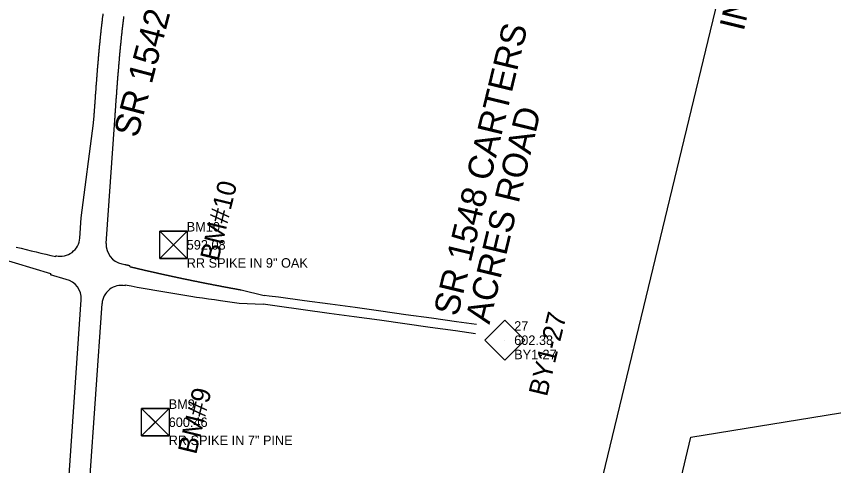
# Model space of a CAD drawing. Extents: x 1649669 to 1659218, y 588594 to 607900.
# Drawn here: x 1655108 to 1656826, y 603109 to 604053 of the extents above; entities that cross this region are included whole.
import ezdxf

# ---------------------------------------------------------------- set-up
doc = ezdxf.new("R2010")
doc.units = 0
for name, color, linetype in [('CTL Bench Mark CELL', 7, 'Continuous'), ('CTL Bench Mark Cogo Comment', 7, 'Continuous'), ('CTL Bench Mark Cogo Elevation', 7, 'Continuous'), ('CTL Bench Mark Cogo Number', 7, 'Continuous'), ('CTL Bench Mark Text', 7, 'Continuous'), ('CTL Sheet Notes CELL', 7, 'Continuous'), ('CTL Supplemental Horizontal and Vertical CELL', 7, 'Continuous'), ('CTL Supplemental Horizontal and Vertical Cogo Comment', 7, 'Continuous'), ('CTL Supplemental Horizontal and Vertical Cogo Elevation', 7, 'Continuous'), ('CTL Supplemental Horizontal and Vertical Cogo Number', 7, 'Continuous'), ('CTL Supplemental Horizontal and Vertical Text', 7, 'Continuous'), ('Default', 7, 'Continuous'), ('Exist Roads EOP', 7, 'Continuous'), ('Sheet Data Field CELL', 7, 'Continuous')]:
    doc.layers.add(name, color=color, linetype=linetype)

msp = doc.modelspace()

# ---------------------------------------------------------------- linework, layer by layer
at = {"layer": 'CTL Bench Mark CELL'}
for p, q in [((1655438.2, 603572.9), (1655438.2, 603572.9)), ((1655400.3, 603200), (1655400.3, 603200))]:
    msp.add_line(p, q, dxfattribs=at)
for points in [[(1655409.4, 603601.6), (1655466.9, 603601.6), (1655466.9, 603544.1), (1655409.4, 603544.1)], [(1655371.5, 603228.7), (1655429, 603228.7), (1655429, 603171.2), (1655371.5, 603171.2)]]:
    msp.add_lwpolyline(points, close=True, dxfattribs=at)
for points in [[(1655466.9, 603601.6), (1655409.4, 603544.1), (1655438.1, 603572.9), (1655466.9, 603544.1), (1655409.4, 603601.6)], [(1655438.1, 603572.9), (1655466.9, 603601.6), (1655409.4, 603601.6), (1655438.1, 603572.9)], [(1655438.1, 603572.9), (1655409.4, 603544.1), (1655466.9, 603544.1), (1655438.1, 603572.9)], [(1655429, 603228.7), (1655371.5, 603171.2), (1655400.3, 603199.9), (1655429, 603171.2), (1655371.5, 603228.7)], [(1655400.3, 603199.9), (1655429, 603228.7), (1655371.5, 603228.7), (1655400.3, 603199.9)], [(1655400.3, 603199.9), (1655371.5, 603171.2), (1655429, 603171.2), (1655400.3, 603199.9)]]:
    msp.add_lwpolyline(points, dxfattribs=at)
at = {"layer": 'CTL Sheet Notes CELL'}
msp.add_lwpolyline([(1656065.2, 601942.6), (1657135.7, 606376.1), (1658875.8, 605955.9), (1657805.4, 601522.5)], close=True, dxfattribs=at)
at = {"layer": 'CTL Supplemental Horizontal and Vertical CELL'}
msp.add_line((1656134.7, 603372.4), (1656134.7, 603372.4), dxfattribs=at)
msp.add_lwpolyline([(1656093, 603372.5), (1656134.9, 603414.5), (1656176.9, 603372.5), (1656135, 603330.5)], close=True, dxfattribs=at)
at = {"layer": 'Default'}
for p, q in [((1656526.1, 603168.4), (1657183.3, 603275.1)), ((1656351.8, 602446.9), (1656526.1, 603168.4))]:
    msp.add_line(p, q, dxfattribs=at)
at = {"layer": 'Exist Roads EOP'}
for p, q in [((1655244.6, 603629.8), (1655270.5, 603828.5)), ((1655270.5, 603828.5), (1655271.2, 603837.9)), ((1655297, 603576.1), (1655315, 603834.8)), ((1655241.6, 603587.2), (1655244.6, 603629.8)), ((1655180.2, 603512), (1654970.5, 603574.3)), ((1655191.5, 603550.2), (1655191.1, 603548.2)), ((1655346.3, 603527.3), (1655346.8, 603529.2)), ((1655396.4, 603515.6), (1655396.4, 603515.6)), ((1655180.2, 603512), (1655179.6, 603510.1)), ((1655212.6, 603500.2), (1655179.6, 603510.1)), ((1655457.5, 603502.2), (1655457.5, 603502.2)), ((1655336.7, 603486.9), (1655337.1, 603488.8)), ((1655518.8, 603489.9), (1655518.8, 603489.9)), ((1655580.4, 603478.2), (1655629.4, 603466.6)), ((1655210.9, 602974.5), (1655244.6, 603457.4)), ((1655254.8, 602971.5), (1655288.2, 603449.4)), ((1655537.3, 603455.9), (1655576.7, 603450.5)), ((1655576.7, 603450.5), (1655626.8, 603447.9)), ((1655713.8, 603455.2), (1655659.3, 603462.6)), ((1655768.1, 603448), (1655713.8, 603455.2)), ((1655820.7, 603441), (1655768.1, 603448)), ((1655711.2, 603436.4), (1655656.7, 603443.8)), ((1655765.4, 603428.9), (1655711.2, 603436.4)), ((1655818.2, 603421.8), (1655765.4, 603428.9)), ((1655874.3, 603433.7), (1655820.7, 603441)), ((1655927.1, 603426.1), (1655874.3, 603433.7)), ((1655871.6, 603414.5), (1655818.2, 603421.8)), ((1655924.8, 603407.1), (1655871.6, 603414.5)), ((1655981, 603418.6), (1655927.1, 603426.1)), ((1656033.6, 603411.2), (1655981, 603418.6)), ((1655978.3, 603399.5), (1655924.8, 603407.1)), ((1656031, 603391.9), (1655978.3, 603399.5)), ((1656075.5, 603405.3), (1656033.6, 603411.2)), ((1656073.6, 603386), (1656031, 603391.9))]:
    msp.add_line(p, q, dxfattribs=at)
for points in [[(1655659.3, 603462.6), (1655639.3, 603465.3), (1655629.4, 603466.6)], [(1655656.7, 603443.8), (1655636.7, 603446.5), (1655626.8, 603447.9)]]:
    msp.add_lwpolyline(points, dxfattribs=at)
for centre, radius, start, end in [((1655200.7, 603590.1), 41, 256.9954, 356.0095), ((1656088, 607432), 3986, 255.7673, 256.9954), ((1655337.9, 603573.2), 41, 176.0095, 258.999), ((1656088, 607432), 3972, 258.999, 259.0872), ((1655203.7, 603460.2), 41, 356.0095, 77.4476), ((1655329.1, 603446.6), 41, 79.2178, 176.0095), ((1656088, 607432), 4014, 259.2178, 262.1141)]:
    msp.add_arc(centre, radius, start, end, dxfattribs=at)
for points in [[(1655271.2, 603837.9), (1655271.4, 603841.6), (1655271.7, 603845.4), (1655271.9, 603849.2), (1655272.2, 603853), (1655272.5, 603856.8), (1655272.7, 603860.5), (1655273, 603864.3), (1655273.3, 603868.1), (1655273.5, 603871.9), (1655273.8, 603875.7), (1655274.1, 603879.4), (1655274.4, 603883.2), (1655274.6, 603887), (1655274.9, 603890.8), (1655275.2, 603894.6), (1655275.5, 603898.3), (1655275.7, 603902.1), (1655276, 603905.9), (1655276.3, 603909.7), (1655276.6, 603913.5), (1655276.9, 603917.3), (1655277.2, 603921.1), (1655277.5, 603924.9), (1655277.8, 603928.6), (1655278.1, 603932.4), (1655278.4, 603936.2), (1655278.7, 603940), (1655279, 603943.8), (1655279.3, 603947.6), (1655279.6, 603951.4), (1655279.9, 603955.2), (1655280.3, 603959), (1655280.6, 603962.8), (1655280.9, 603966.6), (1655281.3, 603970.3), (1655281.6, 603974.1), (1655282, 603977.9), (1655282.3, 603981.7), (1655282.7, 603985.5), (1655283, 603989.3), (1655283.4, 603993.1), (1655283.8, 603996.9), (1655284.1, 604000.7), (1655284.5, 604004.5), (1655284.9, 604008.3), (1655285.3, 604012.1), (1655285.7, 604015.9), (1655286.1, 604019.7), (1655286.5, 604023.5), (1655286.9, 604027.3), (1655287.3, 604031.1), (1655287.8, 604034.9), (1655288.2, 604038.7), (1655288.6, 604042.5), (1655289.1, 604046.3), (1655289.5, 604050), (1655290, 604053.8), (1655290.5, 604057.6), (1655290.6, 604058.7)], [(1655315, 603834.8), (1655315.3, 603838.6), (1655315.6, 603842.4), (1655315.8, 603846.1), (1655316.1, 603849.9), (1655316.4, 603853.7), (1655316.6, 603857.4), (1655316.9, 603861.2), (1655317.2, 603865), (1655317.4, 603868.8), (1655317.7, 603872.5), (1655318, 603876.3), (1655318.2, 603880.1), (1655318.5, 603883.8), (1655318.8, 603887.6), (1655319.1, 603891.3), (1655319.3, 603895.1), (1655319.6, 603898.9), (1655319.9, 603902.6), (1655320.2, 603906.4), (1655320.5, 603910.1), (1655320.8, 603913.9), (1655321, 603917.7), (1655321.3, 603921.4), (1655321.6, 603925.2), (1655321.9, 603928.9), (1655322.2, 603932.7), (1655322.5, 603936.4), (1655322.8, 603940.2), (1655323.2, 603943.9), (1655323.5, 603947.7), (1655323.8, 603951.4), (1655324.1, 603955.2), (1655324.4, 603958.9), (1655324.8, 603962.7), (1655325.1, 603966.4), (1655325.4, 603970.2), (1655325.8, 603973.9), (1655326.1, 603977.7), (1655326.5, 603981.4), (1655326.8, 603985.1), (1655327.2, 603988.9), (1655327.5, 603992.6), (1655327.9, 603996.3), (1655328.3, 604000.1), (1655328.7, 604003.8), (1655329.1, 604007.5), (1655329.4, 604011.3), (1655329.8, 604015), (1655330.2, 604018.7), (1655330.6, 604022.5), (1655331.1, 604026.2), (1655331.5, 604029.9), (1655331.9, 604033.6), (1655332.3, 604037.4), (1655332.8, 604041.1), (1655333.2, 604044.8), (1655333.7, 604048.5), (1655334.1, 604052.2), (1655334.3, 604053.3)], [(1655336.1, 603531.8), (1655336.9, 603531.6), (1655337.7, 603531.4), (1655338.5, 603531.2), (1655339.3, 603531), (1655340.2, 603530.8), (1655341, 603530.6), (1655341.8, 603530.4), (1655342.6, 603530.2), (1655343.4, 603530), (1655344.3, 603529.8), (1655345.1, 603529.6), (1655345.9, 603529.4), (1655346.7, 603529.2), (1655346.8, 603529.2)], [(1655346.3, 603527.3), (1655347.1, 603527.1), (1655347.9, 603526.9), (1655348.7, 603526.7), (1655349.5, 603526.5), (1655350.4, 603526.3), (1655351.2, 603526.1), (1655352, 603525.9), (1655352.8, 603525.7), (1655353.6, 603525.5), (1655354.5, 603525.3), (1655355.3, 603525.1), (1655356.1, 603524.9), (1655356.9, 603524.7), (1655357.8, 603524.5), (1655358.6, 603524.3), (1655359.4, 603524.1), (1655360.2, 603524), (1655361, 603523.8), (1655361.9, 603523.6), (1655362.7, 603523.4), (1655363.5, 603523.2), (1655364.3, 603523), (1655365.1, 603522.8), (1655366, 603522.6), (1655366.8, 603522.4), (1655367.6, 603522.2), (1655368.4, 603522), (1655369.3, 603521.8), (1655370.1, 603521.6), (1655370.9, 603521.4), (1655371.7, 603521.2), (1655372.5, 603521.1), (1655373.4, 603520.9), (1655374.2, 603520.7), (1655375, 603520.5), (1655375.8, 603520.3), (1655376.7, 603520.1), (1655377.5, 603519.9), (1655378.3, 603519.7), (1655379.1, 603519.5), (1655379.9, 603519.3), (1655380.8, 603519.1), (1655381.6, 603519), (1655382.4, 603518.8), (1655383.2, 603518.6), (1655384.1, 603518.4), (1655384.9, 603518.2), (1655385.7, 603518), (1655386.5, 603517.8), (1655387.3, 603517.6), (1655388.2, 603517.4), (1655389, 603517.3), (1655389.8, 603517.1), (1655390.6, 603516.9), (1655391.5, 603516.7), (1655392.3, 603516.5), (1655393.1, 603516.3), (1655393.9, 603516.1), (1655394.8, 603515.9), (1655395.6, 603515.8), (1655396.4, 603515.6)], [(1655396.4, 603515.6), (1655397.2, 603515.4), (1655398, 603515.2), (1655398.9, 603515), (1655399.7, 603514.8), (1655400.5, 603514.6), (1655401.3, 603514.5), (1655402.2, 603514.3), (1655403, 603514.1), (1655403.8, 603513.9), (1655404.6, 603513.7), (1655405.5, 603513.5), (1655406.3, 603513.3), (1655407.1, 603513.2), (1655407.9, 603513), (1655408.8, 603512.8), (1655409.6, 603512.6), (1655410.4, 603512.4), (1655411.2, 603512.2), (1655412.1, 603512.1), (1655412.9, 603511.9), (1655413.7, 603511.7), (1655414.5, 603511.5), (1655415.4, 603511.3), (1655416.2, 603511.1), (1655417, 603511), (1655417.8, 603510.8), (1655418.6, 603510.6), (1655419.5, 603510.4), (1655420.3, 603510.2), (1655421.1, 603510.1), (1655421.9, 603509.9), (1655422.8, 603509.7), (1655423.6, 603509.5), (1655424.4, 603509.3), (1655425.2, 603509.1), (1655426.1, 603509), (1655426.9, 603508.8), (1655427.7, 603508.6), (1655428.5, 603508.4), (1655429.4, 603508.2), (1655430.2, 603508.1), (1655431, 603507.9), (1655431.9, 603507.7), (1655432.7, 603507.5), (1655433.5, 603507.4), (1655434.3, 603507.2), (1655435.2, 603507), (1655436, 603506.8), (1655436.8, 603506.6), (1655437.6, 603506.5), (1655438.5, 603506.3), (1655439.3, 603506.1), (1655440.1, 603505.9), (1655440.9, 603505.7), (1655441.8, 603505.6), (1655442.6, 603505.4), (1655443.4, 603505.2), (1655444.2, 603505), (1655445.1, 603504.9), (1655445.9, 603504.7), (1655446.7, 603504.5), (1655447.5, 603504.3), (1655448.4, 603504.2), (1655449.2, 603504), (1655450, 603503.8), (1655450.8, 603503.6), (1655451.7, 603503.5), (1655452.5, 603503.3), (1655453.3, 603503.1), (1655454.2, 603502.9), (1655455, 603502.8), (1655455.8, 603502.6), (1655456.6, 603502.4), (1655457.5, 603502.2)], [(1655457.5, 603502.2), (1655458.3, 603502.1), (1655459.1, 603501.9), (1655459.9, 603501.7), (1655460.8, 603501.5), (1655461.6, 603501.4), (1655462.4, 603501.2), (1655463.3, 603501), (1655464.1, 603500.9), (1655464.9, 603500.7), (1655465.7, 603500.5), (1655466.6, 603500.3), (1655467.4, 603500.2), (1655468.2, 603500), (1655469, 603499.8), (1655469.9, 603499.7), (1655470.7, 603499.5), (1655471.5, 603499.3), (1655472.4, 603499.1), (1655473.2, 603499), (1655474, 603498.8), (1655474.8, 603498.6), (1655475.7, 603498.5), (1655476.5, 603498.3), (1655477.3, 603498.1), (1655478.1, 603498), (1655479, 603497.8), (1655479.8, 603497.6), (1655480.6, 603497.4), (1655481.5, 603497.3), (1655482.3, 603497.1), (1655483.1, 603496.9), (1655483.9, 603496.8), (1655484.8, 603496.6), (1655485.6, 603496.4), (1655486.4, 603496.3), (1655487.3, 603496.1), (1655488.1, 603495.9), (1655488.9, 603495.8), (1655489.7, 603495.6), (1655490.6, 603495.4), (1655491.4, 603495.3), (1655492.2, 603495.1), (1655493.1, 603494.9), (1655493.9, 603494.8), (1655494.7, 603494.6), (1655495.5, 603494.4), (1655496.4, 603494.3), (1655497.2, 603494.1), (1655498, 603493.9), (1655498.9, 603493.8), (1655499.7, 603493.6), (1655500.5, 603493.4), (1655501.4, 603493.3), (1655502.2, 603493.1), (1655503, 603492.9), (1655503.8, 603492.8), (1655504.7, 603492.6), (1655505.5, 603492.5), (1655506.3, 603492.3), (1655507.2, 603492.1), (1655508, 603492), (1655508.8, 603491.8), (1655509.6, 603491.6), (1655510.5, 603491.5), (1655511.3, 603491.3), (1655512.1, 603491.2), (1655513, 603491), (1655513.8, 603490.8), (1655514.6, 603490.7), (1655515.5, 603490.5), (1655516.3, 603490.3), (1655517.1, 603490.2), (1655517.9, 603490), (1655518.8, 603489.9)], [(1655518.8, 603489.9), (1655519.6, 603489.7), (1655520.4, 603489.5), (1655521.3, 603489.4), (1655522.1, 603489.2), (1655522.9, 603489.1), (1655523.8, 603488.9), (1655524.6, 603488.7), (1655525.4, 603488.6), (1655526.2, 603488.4), (1655527.1, 603488.3), (1655527.9, 603488.1), (1655528.7, 603487.9), (1655529.6, 603487.8), (1655530.4, 603487.6), (1655531.2, 603487.5), (1655532.1, 603487.3), (1655532.9, 603487.2), (1655533.7, 603487), (1655534.6, 603486.8), (1655535.4, 603486.7), (1655536.2, 603486.5), (1655537, 603486.4), (1655537.9, 603486.2), (1655538.7, 603486.1), (1655539.5, 603485.9), (1655540.4, 603485.7), (1655541.2, 603485.6), (1655542, 603485.4), (1655542.9, 603485.3), (1655543.7, 603485.1), (1655544.5, 603485), (1655545.4, 603484.8), (1655546.2, 603484.6), (1655547, 603484.5), (1655547.9, 603484.3), (1655548.7, 603484.2), (1655549.5, 603484), (1655550.4, 603483.9), (1655551.2, 603483.7), (1655552.1, 603483.5), (1655552.9, 603483.4), (1655553.7, 603483.2), (1655554.6, 603483.1), (1655555.4, 603482.9), (1655556.2, 603482.8), (1655557.1, 603482.6), (1655557.9, 603482.5), (1655558.7, 603482.3), (1655559.6, 603482.1), (1655560.4, 603482), (1655561.2, 603481.8), (1655562.1, 603481.7), (1655562.9, 603481.5), (1655563.7, 603481.4), (1655564.6, 603481.2), (1655565.4, 603481), (1655566.2, 603480.9), (1655567.1, 603480.7), (1655567.9, 603480.6), (1655568.7, 603480.4), (1655569.6, 603480.3), (1655570.4, 603480.1), (1655571.2, 603479.9), (1655572.1, 603479.8), (1655572.9, 603479.6), (1655573.8, 603479.5), (1655574.6, 603479.3), (1655575.4, 603479.2), (1655576.3, 603479), (1655577.1, 603478.9), (1655577.9, 603478.7), (1655578.8, 603478.5), (1655580.4, 603478.2)]]:
    msp.add_spline(points, degree=3, dxfattribs=at)

# ---------------------------------------------------------------- texts
at = {"layer": 'CTL Bench Mark Cogo Comment'}
for s, p in [('RR SPIKE IN 9" OAK', (1655466.2, 603524.9)), ('RR SPIKE IN 7" PINE', (1655428.3, 603152))]:
    msp.add_text(s, height=20, dxfattribs=at).set_placement(p)
at = {"layer": 'CTL Bench Mark Cogo Elevation'}
for s, p in [('592.08', (1655466.2, 603562.9)), ('600.46', (1655428.3, 603190))]:
    msp.add_text(s, height=20, dxfattribs=at).set_placement(p)
at = {"layer": 'CTL Bench Mark Cogo Number'}
for s, p in [('BM10', (1655466.2, 603600.9)), ('BM9', (1655428.3, 603228))]:
    msp.add_text(s, height=20, dxfattribs=at).set_placement(p)
at = {"layer": 'CTL Bench Mark Text'}
for s, p in [('BM#10', (1655532.7, 603537)), ('BM#9', (1655486, 603130.8))]:
    msp.add_text(s, height=40, rotation=76.4261, dxfattribs=at).set_placement(p)
at = {"layer": 'CTL Sheet Notes CELL'}
msp.add_text('INSET A', height=52.5, rotation=76.4261, dxfattribs=at).set_placement((1656636.9, 604020.4))
at = {"layer": 'CTL Supplemental Horizontal and Vertical Cogo Comment'}
msp.add_text('BY1-27', height=20, dxfattribs=at).set_placement((1656154.7, 603332.4))
at = {"layer": 'CTL Supplemental Horizontal and Vertical Cogo Elevation'}
msp.add_text('602.38', height=20, dxfattribs=at).set_placement((1656154.7, 603362.4))
at = {"layer": 'CTL Supplemental Horizontal and Vertical Cogo Number'}
msp.add_text('27', height=20, dxfattribs=at).set_placement((1656154.7, 603392.4))
at = {"layer": 'CTL Supplemental Horizontal and Vertical Text'}
msp.add_text('BY1-27', height=40, rotation=76.4261, dxfattribs=at).set_placement((1656223.4, 603252.4))
at = {"layer": 'Sheet Data Field CELL'}
for s, height, rotation, p in [('SR 1542 RIDGE STREET', 52.501, 75.3466, (1655362.9, 603796.2)), ('SR 1548 CARTERS', 52.501, 76.4261, (1656035.8, 603420.6)), ('ACRES ROAD', 52.5, 76.4261, (1656102.7, 603404.5))]:
    msp.add_text(s, height=height, rotation=rotation, dxfattribs=at).set_placement(p)

doc.saveas('drawing.dxf')
